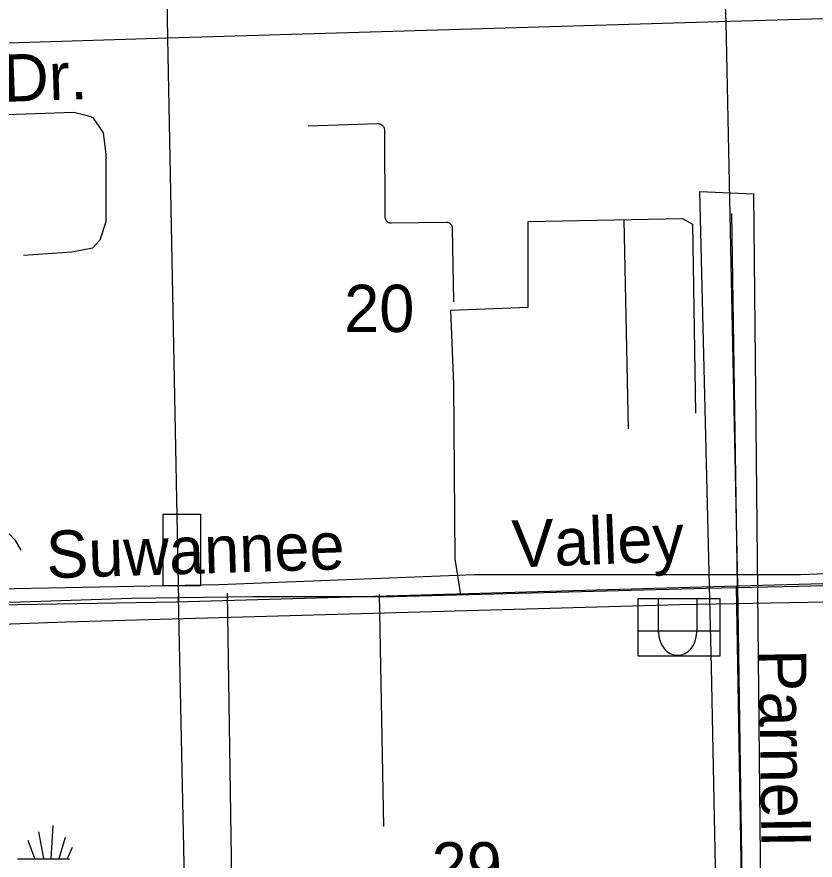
# Model space of a CAD drawing. Extents: x 2480962 to 2688785, y 277103 to 599240.
# Drawn here: x 2521081 to 2528689, y 472131 to 480163 of the extents above; entities that cross this region are included whole.
import ezdxf

# ---------------------------------------------------------------- set-up
doc = ezdxf.new("R2010")
doc.units = 0
for name, color, linetype in [('Culture', 7, 'Continuous'), ('Level 31', 7, 'Continuous'), ('Local Roads Improved', 7, 'Continuous'), ('Local Roads Paved', 7, 'Continuous'), ('Local Roads Related Text', 7, 'Continuous'), ('Section Lines', 7, 'Continuous'), ('Section Numbers', 7, 'Continuous'), ('Swamps', 7, 'Continuous')]:
    doc.layers.add(name, color=color, linetype=linetype)

msp = doc.modelspace()

# ---------------------------------------------------------------- linework, layer by layer
at = {"layer": 'Culture'}
for p, q in [((2527196.669, 474303.572), (2527196.67, 474623.909)), ((2527560.603, 474623.909), (2527560.603, 474303.572)), ((2527780.877, 474312.636), (2527001.307, 474312.636))]:
    msp.add_line(p, q, dxfattribs=at)
msp.add_lwpolyline([(2527780.877, 474074.425), (2527001.307, 474074.425), (2527001.307, 474623.909), (2527780.877, 474623.909)], close=True, dxfattribs=at)
msp.add_ellipse((2527378.636, 474303.571), major_axis=(0, 221.506), ratio=0.82149836, start_param=1.57079633, end_param=4.71238898, dxfattribs=at)
at = {"layer": 'Level 31'}
for points in [[(2527591.304, 478500.867), (2528102.26, 478478.651), (2528235.553, 465216.013), (2527880.105, 465216.013), (2527813.459, 468415.041), (2527702.381, 473968.91)], [(2522475.795, 475425.454), (2522830.462, 475425.454), (2522830.462, 474742.945), (2522475.795, 474742.945)], [(2532724.12, 474659.966), (2532724.12, 475013.62), (2528550.997, 474848.582), (2525438.837, 474848.582), (2523010.409, 474754.274), (2519426.71, 474683.543), (2515159.279, 474542.081), (2513461.737, 474518.504), (2512471.505, 474518.504), (2512259.312, 474447.773), (2512471.505, 474235.58), (2513815.392, 474141.273), (2516314.551, 474212.004), (2521548.637, 474400.619), (2527395.725, 474565.658), (2530012.769, 474612.812)]]:
    msp.add_lwpolyline(points, close=True, dxfattribs=at)
at = {"layer": 'Local Roads Improved'}
for p, q in [((2524519.816, 479143.707), (2523858.307, 479123.274)), ((2524591.949, 478255.529), (2524589.776, 479076.053)), ((2527948.07, 474747.8), (2527895.758, 478290.508)), ((2525175.67, 478205.283), (2524649.899, 478198.474)), ((2525246.192, 477448.398), (2525234.348, 478148.331)), ((2523085.714, 474674.123), (2523140.925, 471044.019)), ((2524534.995, 474660.32), (2524576.403, 472451.892))]:
    msp.add_line(p, q, dxfattribs=at)
for points in [[(2517229.944, 479102.708), (2521623.067, 479255.734), (2521750.588, 479223.854), (2521807.973, 479204.726)], [(2521805.767, 479205.202), (2521903.614, 479058.076), (2521929.119, 478854.041), (2521929.119, 478210.056), (2521871.734, 478037.902), (2521801.597, 477961.389), (2521603.938, 477923.132), (2521144.86, 477891.252)], [(2524589.776, 479076.053), (2524589.385, 479083.146), (2524588.255, 479090.159), (2524586.399, 479097.016), (2524583.836, 479103.641), (2524580.594, 479109.962), (2524576.709, 479115.909), (2524572.224, 479121.418), (2524567.188, 479126.428), (2524561.656, 479130.884), (2524555.688, 479134.737), (2524549.35, 479137.945), (2524542.71, 479140.473), (2524535.844, 479142.293), (2524528.825, 479143.386), (2524521.731, 479143.739), (2524519.816, 479143.707)], [(2524649.899, 478198.474), (2524643.916, 478198.71), (2524637.989, 478199.571), (2524632.186, 478201.046), (2524626.568, 478203.118), (2524621.197, 478205.768), (2524616.133, 478208.964), (2524611.431, 478212.672), (2524607.142, 478216.851), (2524603.314, 478221.456), (2524599.987, 478226.436), (2524597.2, 478231.736), (2524594.982, 478237.298), (2524593.357, 478243.062), (2524592.344, 478248.964), (2524591.953, 478254.94), (2524591.949, 478255.529)], [(2525234.348, 478148.331), (2525233.928, 478154.381), (2525232.879, 478160.354), (2525231.21, 478166.184), (2525228.941, 478171.808), (2525226.097, 478177.164), (2525222.709, 478182.194), (2525218.813, 478186.842), (2525214.453, 478191.057), (2525209.677, 478194.793), (2525204.535, 478198.009), (2525199.086, 478200.671), (2525193.389, 478202.748), (2525187.505, 478204.218), (2525181.5, 478205.065), (2525175.67, 478205.283)], [(2520608.134, 475195.174), (2520652.993, 475233.131), (2520697.851, 475240.033), (2520918.694, 475240.033), (2521008.412, 475240.033), (2521063.622, 475181.371), (2521118.833, 475084.753)]]:
    msp.add_lwpolyline(points, dxfattribs=at)
at = {"layer": 'Local Roads Paved'}
for p, q in [((2526866.511, 478228.66), (2526907.376, 476239.878)), ((2528027.322, 469476.198), (2527940.913, 474739.657)), ((2527948.09, 474746.489), (2528028.339, 469311.838))]:
    msp.add_line(p, q, dxfattribs=at)
for points in [[(2525313.626, 474659.75), (2525259.139, 475000.295), (2525245.517, 476662.154), (2525218.274, 477370.487), (2525953.851, 477397.731), (2525953.851, 477806.384), (2525953.851, 478215.038), (2527425.005, 478242.282), (2527520.357, 478187.795), (2527547.601, 476389.718)], [(2530622.459, 474825.394), (2530507.809, 474790.117), (2528532.299, 474737.202), (2527650.375, 474719.563), (2524678.292, 474640.19), (2523328.948, 474640.19), (2522173.628, 474622.552), (2521115.319, 474587.275), (2520365.684, 474569.636)]]:
    msp.add_lwpolyline(points, dxfattribs=at)
at = {"layer": 'Section Lines'}
for p, q in [((2527608.778, 485490.274), (2527837.602, 480111.411)), ((2522521.166, 479959.3), (2522463.351, 483277.354)), ((2533199.703, 480269.467), (2527878.024, 480119.717)), ((2527878.024, 480119.717), (2522521.166, 479959.3)), ((2527837.601, 480111.411), (2527948.3, 474746.336)), ((2522521.222, 479959.302), (2511957.581, 479642.963)), ((2522623.919, 474594.146), (2522521.222, 479959.302)), ((2533286.715, 474891.598), (2527958.459, 474740.156)), ((2527940.913, 474739.657), (2522599.794, 474587.849)), ((2528027.322, 469476.198), (2527940.913, 474739.657)), ((2522731.101, 469307.197), (2522623.012, 474641.879)), ((2522599.794, 474587.849), (2517360.25, 474498.421))]:
    msp.add_line(p, q, dxfattribs=at)
at = {"layer": 'Swamps'}
for p, q in [((2521409.229, 472145.127), (2521426.465, 472461.201)), ((2521338.23, 472145.176), (2521291.974, 472399.557)), ((2521253.156, 472145.264), (2521187.682, 472317.128)), ((2521485.915, 472145.306), (2521544.147, 472349.126))]:
    msp.add_line(p, q, dxfattribs=at)
for points in [[(2521562.511, 472145.23), (2521611.394, 472253.862)], [(2521087.721, 472145.09), (2521582.643, 472145.098)]]:
    msp.add_lwpolyline(points, dxfattribs=at)

# ---------------------------------------------------------------- texts
at = {"layer": 'Local Roads Related Text'}
for s, rotation, p in [('NW Sophie Dr.', 2.0009333, (2517749.695, 479241.178)), ('Valley', 2.2329111, (2525809.338, 474917.183)), ('Suwannee', 1.7633222, (2521367.634, 474815.86)), ('Parnell      Ave.', 270.7377333, (2528153.5, 474137.279))]:
    msp.add_text(s, height=450, rotation=rotation, dxfattribs=at).set_placement(p)
at = {"layer": 'Section Numbers'}
for s, rotation, p in [('20', 359.9794222, (2524200.602, 477161.737)), ('29', 359.9794306, (2525034.387, 471852.12))]:
    msp.add_text(s, height=450, rotation=rotation, dxfattribs=at).set_placement(p)

doc.saveas('drawing.dxf')
